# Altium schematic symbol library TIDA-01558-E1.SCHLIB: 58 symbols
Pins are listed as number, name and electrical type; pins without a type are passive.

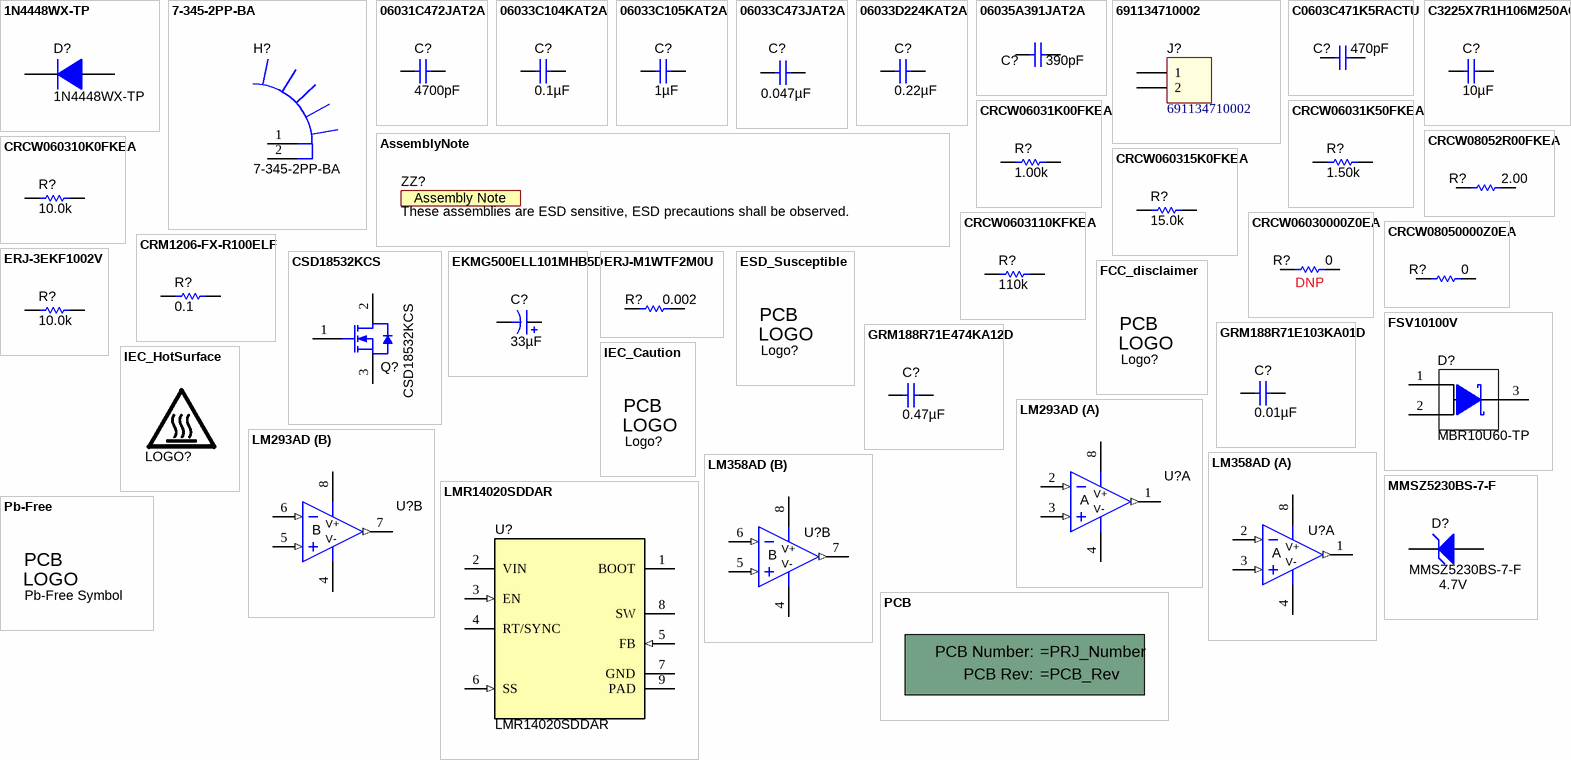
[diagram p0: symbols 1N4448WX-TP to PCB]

## 1N4448WX-TP
designator D?
Diode, Switching, 75 V, 0.25 A, SOD-323; Manufacturer: Micro Commercial Components; U/M: EA; Value: 75V; Value1: 0.25A; Io_A: 0.25; Vr_V: 75; TJmax_C: 150; SizeAreaWB_mm2: 8.695; SizeArea_mm2: 3.645; SizeX_mm: 2.7; SizeY_mm: 1.35; SizeZ_mm: 1; AEC Category: Q101; Green_Lifecycle: Not Set; Green_REACh: Incomplete
signal-integrity model Diode
footprint SOD-323
pins: 1 K, 2 A

## 7-345-2PP-BA
designator H?
Heatsink, TO-220, Black Anodized; Manufacturer: CTS Electrocomponents; SymbolCreator: a0799628
footprint HEATSINK_7-340-2PP (HEATSINK, DUAL TO-220)
pins: 1, 2

## 06031C472JAT2A
designator C?  ValueDisplayed: 4700pF  (hidden comment: 06031C472JAT2A)
CAP, CERM, 4700 pF, 100 V,+/- 5%, X7R, 0603; Manufacturer: AVX; Polarized: N; CompType: Capacitor; Value: 4700pF; U/M: EA; Cap_F: 0.0000000047; Tolerance_%: 5; ESR_ohm: 0.136; Value1: 0.136 ohm; VDC_V: 100; Value2: 100V; TaMin_C: -55; TaMax_C: 125; Cap_Case: 0603; SizeArea_mm2: 1.28; SizeAreaWB_mm2: 4.68; SizeX_mm: 1.6; SizeY_mm: 0.8; SizeZ_mm: 1; AEC Category: Q200; Green_Lifecycle: Active; Green_REACh: Passed
signal-integrity model Cap
simulation model Cap
footprint 0603
footprint 0603M
footprint 0603L
footprint 0603_HV
footprint 0603S
pins: 1, 2

## 06033C104KAT2A
designator C?  ValueDisplayed: 0.1µF  (hidden comment: 06033C104KAT2A)
CAP, CERM, 0.1 µF, 25 V,+/- 10%, X7R, 0603; Manufacturer: AVX; Polarized: N; CompType: Capacitor; Value: 0.1uF; U/M: EA; Cap_F: 0.0000001; Tolerance_%: 10; ESR_ohm: 0.05; Value1: 0.05 ohm; VDC_V: 25; Value2: 25V; TaMin_C: -55; TaMax_C: 125; Cap_Case: 0603; SizeArea_mm2: 1.28; SizeAreaWB_mm2: 4.68; SizeX_mm: 1.6; SizeY_mm: 0.8; SizeZ_mm: 1; AEC Category: Q200; Green_Lifecycle: Active; Green_REACh: Passed
signal-integrity model Cap
simulation model Cap
footprint 0603
footprint 0603M
footprint 0603L
footprint 0603_HV
footprint 0603S
pins: 1, 2

## 06033C105KAT2A
designator C?  ValueDisplayed: 1µF  (hidden comment: 06033C105KAT2A)
CAP, CERM, 1 µF, 25 V,+/- 10%, X7R, 0603; Manufacturer: AVX; Polarized: N; CompType: Capacitor; Value: 1uF; U/M: EA; Cap_F: 0.000001; Tolerance_%: 10; Value1: Unknown; VDC_V: 25; Value2: 25V; TaMin_C: -55; TaMax_C: 125; Cap_Case: 0603; SizeArea_mm2: 1.28; SizeAreaWB_mm2: 4.68; SizeX_mm: 1.6; SizeY_mm: 0.8; SizeZ_mm: 1; AEC Category: Q200
signal-integrity model Cap
simulation model Cap
footprint 0603
footprint 0603M
footprint 0603L
footprint 0603_HV
footprint 0603S
pins: 1, 2

## 06033C473JAT2A
designator C?  ValueDisplayed: 0.047µF  (hidden comment: 06033C473JAT2A)
CAP, CERM, 0.047 µF, 25 V,+/- 5%, X7R, 0603; Manufacturer: AVX; Polarized: N; CompType: Capacitor; Value: 0.047uF; U/M: EA; Cap_F: 0.000000047; Tolerance_%: 5; ESR_ohm: 0.052; Value1: 0.052 ohm; VDC_V: 25; Value2: 25V; TaMin_C: -55; TaMax_C: 125; Cap_Case: 0603; SizeArea_mm2: 1.28; SizeAreaWB_mm2: 4.68; SizeX_mm: 1.6; SizeY_mm: 0.8; SizeZ_mm: 1; AEC Category: Q200; Green_Lifecycle: Active; Green_REACh: Passed
signal-integrity model Cap
simulation model Cap
footprint 0603
footprint 0603M
footprint 0603L
footprint 0603_HV
footprint 0603S
pins: 1, 2

## 06033D224KAT2A
designator C?  ValueDisplayed: 0.22µF  (hidden comment: 06033D224KAT2A)
CAP, CERM, 0.22 µF, 25 V,+/- 10%, X5R, 0603; Manufacturer: AVX; Polarized: N; CompType: Capacitor; Value: 0.22uF; U/M: EA; Cap_F: 0.00000022; Tolerance_%: 10; ESR_ohm: 0.036; Value1: 0.036 ohm; VDC_V: 25; Value2: 25V; TaMin_C: -55; TaMax_C: 85; Cap_Case: 0603; SizeArea_mm2: 1.28; SizeAreaWB_mm2: 4.68; SizeX_mm: 1.6; SizeY_mm: 0.8; SizeZ_mm: 1; AEC Category: Q200; Green_Lifecycle: Active; Green_REACh: Passed
signal-integrity model Cap
simulation model Cap
footprint 0603
footprint 0603M
footprint 0603L
footprint 0603_HV
footprint 0603S
pins: 1, 2

## 06035A391JAT2A
designator C?  ValueDisplayed: 390pF  (hidden comment: 06035A391JAT2A)
CAP, CERM, 390 pF, 50 V,+/- 5%, C0G/NP0, 0603; Manufacturer: AVX; Polarized: N; CompType: Capacitor; Value: 390pF; U/M: EA; Cap_F: 0.00000000039; Tolerance_%: 5; ESR_ohm: 0.067; Value1: 0.067 ohm; VDC_V: 50; Value2: 50V; TaMin_C: -55; TaMax_C: 125; Cap_Case: 0603; SizeArea_mm2: 1.28; SizeAreaWB_mm2: 4.68; SizeX_mm: 1.6; SizeY_mm: 0.8; SizeZ_mm: 1; AEC Category: Q200; Green_Lifecycle: Not Set; Green_REACh: Incomplete
signal-integrity model Cap
simulation model Cap
footprint 0603
footprint 0603M
footprint 0603L
footprint 0603_HV
footprint 0603S
pins: 1, 2

## 691134710002
designator J?
WR-TBL Serie 1347 - 5.00 mm Horizontal Cable Entry with Pressure Clamp, 02p; Manufacturer: Wurth Elektronik; Pitch: 5 mm
footprint 691134710002 (Serie 1347 - 5.00 mm_2 pins)
pins: 1, 2

## AssemblyNote
designator ZZ?, comment These assemblies are ESD sensitive, ESD precautions shall be observed.  (no BOM)
SymbolCreator: codlsc; CompType: AssemblyNote
footprint AssemblyNote

## C0603C471K5RACTU
designator C?, comment ValueDisplayed: 470pF  (hidden comment: C0603C471K3RACTU)
CAP, CERM, 470 pF, 25 V,+/- 10%, X7R, 0603; Manufacturer: Kemet; Polarized: N; CompType: Capacitor; Value: 470pF; U/M: EA; Cap_F: 0.00000000047; Tolerance_%: 10; VDC_V: 25; Value2: 25V; TaMin_C: -55; TaMax_C: 125; Cap_Case: 0603; SizeArea_mm2: 1.28; SizeAreaWB_mm2: 4.68; SizeX_mm: 1.6; SizeY_mm: 0.8; SizeZ_mm: 1; AEC Category: Q200; Green_Lifecycle: Active; Green_REACh: Passed
signal-integrity model Cap
simulation model Cap
footprint 0603
footprint 0603M
footprint 0603L
footprint 0603_HV
footprint 0603S
pins: 1, 2

## C3225X7R1H106M250AC
designator C?  ValueDisplayed: 10µF  (hidden comment: C3225X7R1H106M250AC)
CAP, CERM, 10 µF, 50 V,+/- 20%, X7R, 1210; Manufacturer: TDK; Polarized: N; CompType: Capacitor; Value: 10uF; U/M: EA; Cap_F: 0.00001; Tolerance_%: 20; VDC_V: 50; Value2: 50V; TaMin_C: -55; TaMax_C: 125; Cap_Case: 1210; SizeArea_mm2: 8; SizeAreaWB_mm2: 14.7; SizeX_mm: 3.2; SizeY_mm: 2.5; SizeZ_mm: 2.8; AEC Category: Q200; Green_Lifecycle: Active; Green_REACh: Passed
signal-integrity model Cap
simulation model Cap
footprint 1210_280
pins: 1, 2

## CRCW06031K00FKEA
designator R?  ValueDisplayed: 1.00k  (hidden comment: CRCW06031K00FKEA)
RES, 1.00 k, 1%, 0.1 W, 0603; Manufacturer: Vishay-Dale; CompType: Resistor; Value: 1.00k; Res_ohm: 1000; Value_Code: 1k00; Tolerance_%: 1; Power_W: 0.1; Value2: 0.1W; VDC_V: 75; TempCo: 100 ppm/C; SizeArea_mm2: 1.28; SizeX_mm: 1.6; SizeY_mm: 0.8; EIA_Code: E96; U/M: EA; AEC Category: Q200; Green_Lifecycle: Active; Green_REACh: Passed
signal-integrity model Resistor
simulation model Resistor
footprint 0603
footprint 0603M
footprint 0603L
footprint 0603_HV
footprint 0603S
pins: 1, 2

## CRCW06031K50FKEA
designator R?  ValueDisplayed: 1.50k  (hidden comment: CRCW06031K50FKEA)
RES, 1.50 k, 1%, 0.1 W, 0603; Manufacturer: Vishay-Dale; CompType: Resistor; Value: 1.50k; Res_ohm: 1500; Value_Code: 1k50; Tolerance_%: 1; Power_W: 0.1; Value2: 0.1W; VDC_V: 75; TempCo: 100 ppm/C; SizeArea_mm2: 1.28; SizeX_mm: 1.6; SizeY_mm: 0.8; EIA_Code: E96; U/M: EA; AEC Category: Q200; Green_Lifecycle: Active; Green_REACh: Passed
signal-integrity model Resistor
simulation model Resistor
footprint 0603
footprint 0603M
footprint 0603L
footprint 0603_HV
footprint 0603S
pins: 1, 2

## CRCW08052R00FKEA
designator R?  ValueDisplayed: 2.00  (hidden comment: CRCW08052R00FKEA)
RES, 2.00, 1%, 0.125 W, 0805; Manufacturer: Vishay-Dale; CompType: Resistor; Value: 2.00; Res_ohm: 2; Value_Code: 2R00; Tolerance_%: 1; Power_W: 0.125; Value2: 0.125W; VDC_V: 150; TempCo: 100 ppm/C; SizeArea_mm2: 2.5; SizeY_mm: 1.25; SizeZ_mm: 1.45; EIA_Code: E96; U/M: EA; AEC Category: Q200
signal-integrity model Resistor
simulation model Resistor
footprint 0805_HV
footprint 0805_HV1
footprint 0805
footprint 0805M
footprint 0805L
pins: 1, 2

## CRCW060310K0FKEA
designator R?  ValueDisplayed: 10.0k  (hidden comment: CRCW060310K0FKEA)
RES, 10.0 k, 1%, 0.1 W, 0603; Manufacturer: Vishay-Dale; CompType: Resistor; Value: 10.0k; Res_ohm: 10000; Value_Code: 10k0; Tolerance_%: 1; Power_W: 0.1; Value2: 0.1W; VDC_V: 75; TempCo: 100 ppm/C; SizeArea_mm2: 1.28; SizeX_mm: 1.6; SizeY_mm: 0.8; EIA_Code: E96; U/M: EA; AEC Category: Q200; Green_Lifecycle: Active; Green_REACh: Passed
signal-integrity model Resistor
simulation model Resistor
footprint 0603
footprint 0603M
footprint 0603L
footprint 0603_HV
footprint 0603S
pins: 1, 2

## CRCW060315K0FKEA
designator R?  ValueDisplayed: 15.0k  (hidden comment: CRCW060315K0FKEA)
RES, 15.0 k, 1%, 0.1 W, 0603; Manufacturer: Vishay-Dale; CompType: Resistor; Value: 15.0k; Res_ohm: 15000; Value_Code: 15k0; Tolerance_%: 1; Power_W: 0.1; Value2: 0.1W; VDC_V: 75; TempCo: 100 ppm/C; SizeArea_mm2: 1.28; SizeX_mm: 1.6; SizeY_mm: 0.8; EIA_Code: E96; U/M: EA; AEC Category: Q200; Green_Lifecycle: Active; Green_REACh: Passed
signal-integrity model Resistor
simulation model Resistor
footprint 0603
footprint 0603M
footprint 0603L
footprint 0603_HV
footprint 0603S
pins: 1, 2

## CRCW0603110KFKEA
designator R?  ValueDisplayed: 110k  (hidden comment: CRCW0603110KFKEA)
RES, 110 k, 1%, 0.1 W, 0603; Manufacturer: Vishay-Dale; CompType: Resistor; Value: 110k; Res_ohm: 110000; Tolerance_%: 1; Power_W: 0.1; Value2: 0.1W; VDC_V: 75; TempCo: 100 ppm/C; SizeArea_mm2: 1.28; SizeX_mm: 1.6; SizeY_mm: 0.8; EIA_Code: E96; U/M: EA; AEC Category: Q200; Green_Lifecycle: Active; Green_REACh: Passed
signal-integrity model Resistor
simulation model Resistor
footprint 0603
footprint 0603M
footprint 0603L
footprint 0603_HV
footprint 0603S
pins: 1, 2

## CRCW06030000Z0EA
designator R?  ValueDisplayed: 0  Installation: DNP  (hidden comment: CRCW06030000Z0EA)
RES, 0, 5%, 0.1 W, 0603; Manufacturer: Vishay-Dale; CompType: Resistor; Value: 0; Value_Code: 0000; Tolerance_%: 5; Power_W: 0.1; Value2: 0.1W; VDC_V: 75; TempCo: 200 ppm/C; SizeArea_mm2: 1.28; SizeX_mm: 1.6; SizeY_mm: 0.8; SizeZ_mm: 1; EIA_Code: E24; U/M: EA; AEC Category: Q200; Green_Lifecycle: Active; Green_REACh: Passed
signal-integrity model Resistor
simulation model Resistor
footprint 0603
footprint 0603M
footprint 0603L
footprint 0603_HV
footprint 0603S
pins: 1, 2

## CRCW08050000Z0EA
designator R?  ValueDisplayed: 0  (hidden comment: CRCW08050000Z0EA)
RES, 0, 5%, 0.125 W, 0805; Manufacturer: Vishay-Dale; CompType: Resistor; Value: 0; Value_Code: 0000; Tolerance_%: 5; Power_W: 0.125; Value2: 0.125W; VDC_V: 150; TempCo: 200 ppm/C; SizeArea_mm2: 2.5; SizeX_mm: 2; SizeY_mm: 1.25; SizeZ_mm: 1.45; EIA_Code: E24; U/M: EA; AEC Category: Q200; Green_Lifecycle: Active; Green_REACh: Passed
signal-integrity model Resistor
simulation model Resistor
footprint 0805_HV
footprint 0805_HV1
footprint 0805
footprint 0805M
footprint 0805L
pins: 1, 2

## CRM1206-FX-R100ELF
designator R?  ValueDisplayed: 0.1  (hidden comment: CRM1206-FX-R100ELF)
RES, 0.1, 1%, 0.5 W, 1206; Manufacturer: Bourns; CompType: Resistor; Value: 0.1; Value_Code: R100; Tolerance_%: 1; Power_W: 0.5; Value2: 0.5W; VDC_V: 0; TempCo: 150 ppm/C; SizeArea_mm2: 5.12; SizeX_mm: 3.2; SizeY_mm: 1.6; SizeZ_mm: 1.35; EIA_Code: E96; U/M: EA; AEC Category: Q200
signal-integrity model Resistor
simulation model Resistor
footprint 1206
footprint 1206M
footprint 1206L
pins: 1, 2

## CSD18532KCS
designator Q?
MOSFET, N-CH, 60 V, 100 A, KCS0003B (TO-220-3); Manufacturer: Texas Instruments; Alternate Manufacturer: None; U/M: EA; ChType: N; Value: 60V; VdsMax_V: 60; Value1: 0.0053 ohm; Rdson45_ohm: 0.0053; Value2: 44 nC; QgTyp_nC: 44; Vgs_V: 20; IdsMax_A: 100; SizeAreaWB_mm2: 79.648; SizeArea_mm2: 46.228; SizeX_mm: 4.55; SizeY_mm: 10.16; SizeZ_mm: 20.45; AEC Category: Q101
footprint TO-220AB_Horizontal_100mil (High Voltage staggered pins)
footprint KCS0003B_FormA
pins: 1 G, 2 D, 3 S
1 alternate drawing of the same symbol

## EKMG500ELL101MHB5D
designator C?, comment ValueDisplayed: 33µF  (hidden comment: 63SXE33M)
CAP, AL, 33 µF, 63 V, +/- 20%, TH; Manufacturer: Panasonic Electronic Components; Polarized: Y; CompType: Capacitor; Value: 33uF; U/M: EA; Cap_F: 0.0001; Tolerance_%: 20; VDC_V: 63; Value2: 63V; IRMS_A: 0.18; TaMin_C: -55; TaMax_C: 105; Cap_Case: 8x11.5mm; SizeAreaWB_mm2: 100; SizeArea_mm2: 64; SizeX_mm: 8; SizeZ_mm: 13; AEC Category: Q200; AEC Qualified: N
signal-integrity model Cap
simulation model Cap
footprint Chemi-Con_800x1150
pins: 1 +, 2 -

## ERJ-3EKF1002V
designator R?  ValueDisplayed: 10.0k  (hidden comment: ERJ-3EKF1002V)
RES, 10.0 k, 1%, 0.1 W, 0603; Manufacturer: Panasonic; CompType: Resistor; Value: 10.0k; Res_ohm: 10000; Value_Code: 10k0; Tolerance_%: 1; Power_W: 0.1; Value2: 0.1W; VDC_V: 75; TempCo: 100 ppm/C; SizeArea_mm2: 1.28; SizeX_mm: 1.6; SizeY_mm: 0.8; EIA_Code: E96; U/M: EA; AEC Category: Q200; Green_Lifecycle: Active; Green_REACh: Passed
signal-integrity model Resistor
simulation model Resistor
footprint 0603
footprint 0603M
footprint 0603L
footprint 0603_HV
footprint 0603S
pins: 1, 2

## ERJ-M1WTF2M0U
designator R?, comment ValueDisplayed: 0.002  (hidden comment: CRE2512-FZ-R002E-3)
RES SMD 2 MOHM 1% 3W 2512; Manufacturer: Bourns Inc.; CompType: Resistor; Value: 0.002; Value_Code: 2L000; Tolerance_%: 1; TempCo: ppm/C; SizeArea_mm2: 20.16; SizeX_mm: 6.3; SizeY_mm: 3.2; SizeZ_mm: 0.71; U/M: EA; AEC Category: Q200
signal-integrity model Resistor
simulation model Resistor
footprint 2512
footprint 2512M
footprint 2512L
pins: 1, 2

## ESD_Susceptible
designator Logo?, comment ESD Susceptible  (value not drawn)  (no BOM)
ESD Susceptible Symbol; SymbolCreator: a0412235
footprint ESD_Overlay_Large
footprint ESD_Overlay_Medium
footprint ESD_Overlay_Small

## FCC_disclaimer
designator Logo?, comment FCC disclaimer  (value not drawn)  (no BOM)
FCC_disclaimer; SymbolCreator: a0412235
footprint FCC_disclaimer
footprint FCC_disclaimer_stacked

## FSV10100V
designator D?, comment MBR10U60-TP
DIODE SCHOTTKY 60V 10A TO277; Manufacturer: Micro Commercial Co; U/M: EA; Vf_V: 500mV; Io_A: 10; TJmax_C: 150; SizeAreaWB_mm2: 57.375; SizeArea_mm2: 30.875; SizeX_mm: 6.5; SizeY_mm: 4.75; SizeZ_mm: 1.2; AEC Category: Q101; AEC Qualified: Y; Green_Lifecycle: Not Set; Green_REACh: Incomplete
signal-integrity model Diode
footprint TO-277A
pins: 1 A, 2 A, 3 K

## GRM188R71E103KA01D
designator C?  ValueDisplayed: 0.01µF  (hidden comment: GRM188R71E103KA01D)
CAP, CERM, 0.01 µF, 25 V,+/- 10%, X7R, 0603; Manufacturer: MuRata; Polarized: N; CompType: Capacitor; Value: 0.01uF; U/M: EA; Cap_F: 0.00000001; Tolerance_%: 10; Value1: Unknown; VDC_V: 25; Value2: 25V; TaMin_C: -55; TaMax_C: 125; Cap_Case: 0603; SizeArea_mm2: 1.28; SizeAreaWB_mm2: 4.68; SizeX_mm: 1.6; SizeY_mm: 0.8; SizeZ_mm: 1; AEC Category: Q200; Green_Lifecycle: Active; Green_REACh: Passed
signal-integrity model Cap
simulation model Cap
footprint 0603
footprint 0603M
footprint 0603L
footprint 0603_HV
footprint 0603S
pins: 1, 2

## GRM188R71E474KA12D
designator C?  ValueDisplayed: 0.47µF  (hidden comment: GRM188R71E474KA12D)
CAP, CERM, 0.47 µF, 25 V,+/- 10%, X7R, 0603; Manufacturer: MuRata; Polarized: N; CompType: Capacitor; Value: 0.47uF; U/M: EA; Cap_F: 0.00000047; Tolerance_%: 10; VDC_V: 25; Value2: 25V; TaMin_C: -55; TaMax_C: 125; Cap_Case: 0603; SizeArea_mm2: 1.28; SizeAreaWB_mm2: 4.68; SizeX_mm: 1.6; SizeY_mm: 0.8; SizeZ_mm: 1; AEC Category: Q200; Green_Lifecycle: Active; Green_REACh: Passed
signal-integrity model Cap
simulation model Cap
footprint 0603
footprint 0603M
footprint 0603L
footprint 0603_HV
footprint 0603S
pins: 1, 2

## IEC_Caution
designator Logo?, comment CAUTION.  READ USER GUIDE BEFORE USE  (value not drawn)  (no BOM)
IEC 61010-1 Caution Warning; SymbolCreator: a0412235
footprint IEC_Caution_Large
footprint IEC_Caution_Medium
footprint IEC_Caution_Small

## IEC_HotSurface
designator LOGO?, comment CAUTION HOT SURFACE  (value not drawn)  (no BOM)
IEC 61010-1 Hot Surface Warning; SymbolCreator: a0412235
footprint IEC_HotSurface_Large
footprint IEC_HotSurface_Medium
footprint IEC_HotSurface_Small

## LM293AD
designator U?  (value not drawn)
Dual Comparator, D0008A; Manufacturer: Texas Instruments; CompType: OpAmp IC
footprint D0008A_N
footprint D0008A_M
footprint D0008A_L
simulation model LM293A (SUBCKT)
pins on every part: 4 V- (power), 8 V+ (power)
part A pins: 1 OUT (out), 2 IN- (in), 3 IN+ (in)
part B pins: 5 IN+ (in), 6 IN- (in), 7 OUT (out)
1 alternate drawing of the same symbol

## LM358AD
designator U?  (value not drawn)
Dual Low Power Op Amp, D0008A; Manufacturer: Texas Instruments; CompType: OpAmp IC
footprint D0008A_N
footprint D0008A_M
footprint D0008A_L
simulation model LM358 (SUBCKT)
pins on every part: 4 V- (power), 8 V+ (power)
part A pins: 1 OUT (out), 2 IN- (in), 3 IN+ (in)
part B pins: 5 IN+ (in), 6 IN- (in), 7 OUT (out)
1 alternate drawing of the same symbol

## LMR14020SDDAR
designator U?
SIMPLE SWITCHER, 4V to 40V, 2A 2.2MHz Step-Down Regulator with Low IQ, DDA0008E (SOIC-8); Manufacturer: Texas Instruments; SymbolCreator: Altium; SizeArea_mm2: 31; SizeAreaWB_mm2: 57.4; SizeX_mm: 5; SizeY_mm: 6.2; SizeZ_mm: 1.7; CompType: IC; U/M: EA
footprint DDA0008E_N
footprint DDA0008E_M
footprint DDA0008E_L
pins: 1 BOOT, 2 VIN (power), 3 EN (in), 4 RT/SYNC, 5 FB (in), 6 SS (in), 7 GND (power), 8 SW (power), 9 PAD (power)

## MMSZ5230BS-7-F
designator D?  value 4.7V
Diode, Zener, 4.7 V, 200 mW, SOD-323; Manufacturer: Diodes Inc.; SymbolCreator: a0412235; U/M: EA; Power_W: 0.2; Vz_V: 4.7; Value1: 0.2W; RJA_CperW: 350; SizeAreaWB_mm2: 8.695; SizeArea_mm2: 3.645; SizeX_mm: 2.7; SizeY_mm: 1.35; SizeZ_mm: 1; AEC Category: Q101; Green_Lifecycle: Active; Green_REACh: Passed
signal-integrity model Diode
footprint SOD-323
pins: 1 K, 2 A

## Pb-Free
designator Logo?, comment Pb-Free Symbol  (no BOM)
SymbolCreator: a0412235
footprint Pb-Free_Overlay_Medium
footprint Pb-Free_Overlay_Small

## PCB
designator !PCB?, comment Printed Circuit Board  (value not drawn)  (mechanical)
Manufacturer: Any; SymbolCreator: a0412235; CompType: PCB
1 alternate drawing of the same symbol

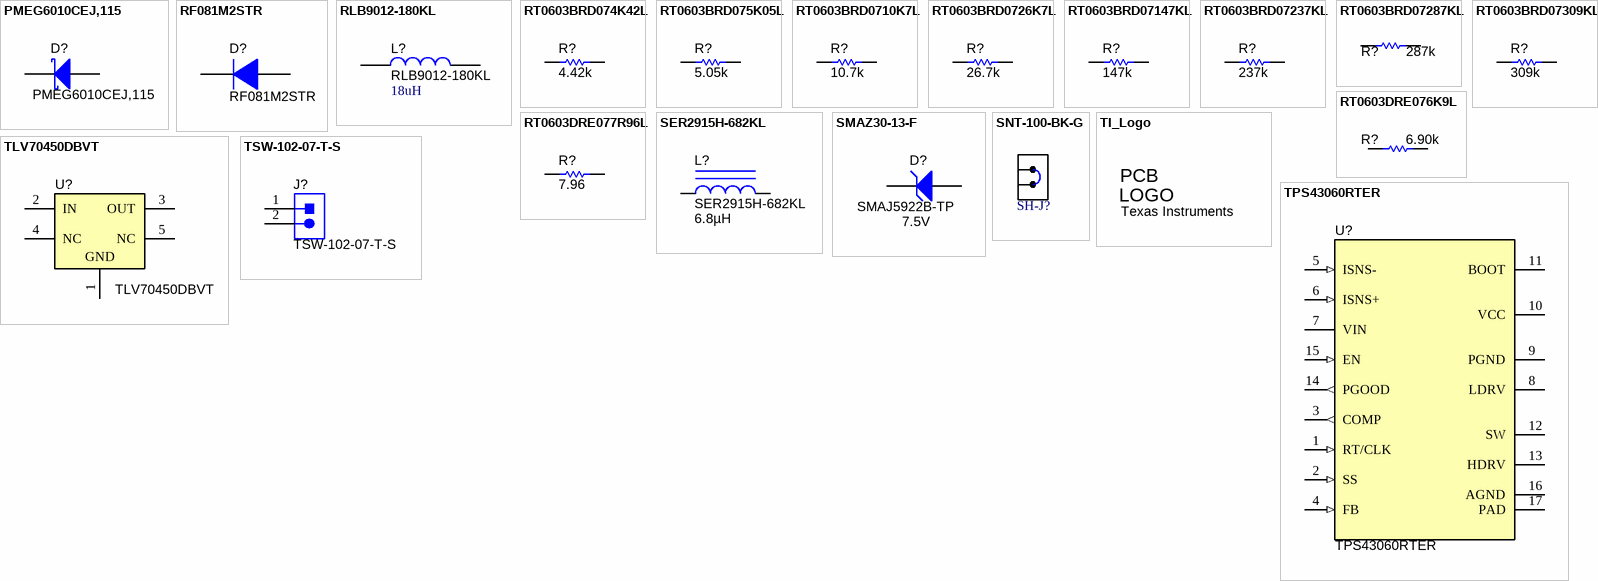
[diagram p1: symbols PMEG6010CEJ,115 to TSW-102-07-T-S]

## PMEG6010CEJ,115
designator D?
Diode, Schottky, 60 V, 1 A, SOD-323F; Manufacturer: Nexperia; U/M: EA; Vf_V: 0.66; Value: 60V; Value1: 1A; Value2: 0.66V; Io_A: 1; Vr_V: 60; TJmax_C: 150; SizeAreaWB_mm2: 7.875; SizeArea_mm2: 3.125; SizeX_mm: 2.5; SizeY_mm: 1.25; SizeZ_mm: 0.8; AEC Category: Q101; Green_Lifecycle: Not Set; Green_REACh: Incomplete
signal-integrity model Diode
footprint SOD-323F
pins: 1 K, 2 A

## RF081M2STR
designator D?
Diode, Fast Rectifier, 200 V, 0.8 A, SOD-123; Manufacturer: Rohm; U/M: EA; Vf_V: 0.95; Value: 200V; Value1: 0.8A; Value2: 0.95V; Io_A: 0.8; Vr_V: 200; TJmax_C: 150; SizeAreaWB_mm2: 13.095; SizeArea_mm2: 6.545; SizeX_mm: 3.85; SizeY_mm: 1.7; SizeZ_mm: 1.35; AEC Category: Q101; Green_Lifecycle: Not Set; Green_REACh: Incomplete
signal-integrity model Diode
footprint SOD-123
pins: 1 K, 2 A

## RLB9012-180KL
designator L?  value 18uH
INDUCTOR, FIXED, 18uH, 10%, 2.66A, 11MHz, TH, 2-PIN; Manufacturer: BOURNS; SymbolCreator: x0199378
footprint IND_RLB9012 (INDUCTOR, RLB9012 SERIES, 2-PIN)
pins: 1, 2

## RT0603BRD074K42L
designator R?  ValueDisplayed: 4.42k  (hidden comment: RT0603BRD074K42L)
RES, 4.42 k, 0.1%, 0.1 W, 0603; Manufacturer: Yageo America; CompType: Resistor; Value: 4.42k; Res_ohm: 4420; Value_Code: 4k42; Tolerance_%: 0.1; Value2: 0.1W; VDC_V: 75; TempCo: 25 ppm/C; SizeArea_mm2: 1.28; SizeX_mm: 1.6; SizeY_mm: 0.8; SizeZ_mm: 1; EIA_Code: E192; U/M: EA; AEC Category: Q200
signal-integrity model Resistor
simulation model Resistor
footprint 0603
footprint 0603M
footprint 0603L
footprint 0603_HV
footprint 0603S
pins: 1, 2

## RT0603BRD075K05L
designator R?  ValueDisplayed: 5.05k  (hidden comment: RT0603BRD075K05L)
RES, 5.05 k, 0.1%, 0.1 W, 0603; Manufacturer: Yageo America; CompType: Resistor; Value: 5.05k; Res_ohm: 5050; Value_Code: 5k05; Tolerance_%: 0.1; Value2: 0.1W; VDC_V: 75; TempCo: 25 ppm/C; SizeArea_mm2: 1.28; SizeX_mm: 1.6; SizeY_mm: 0.8; SizeZ_mm: 1; EIA_Code: E192; U/M: EA; AEC Category: Q200
signal-integrity model Resistor
simulation model Resistor
footprint 0603
footprint 0603M
footprint 0603L
footprint 0603_HV
footprint 0603S
pins: 1, 2

## RT0603BRD0710K7L
designator R?  ValueDisplayed: 10.7k  (hidden comment: RT0603BRD0710K7L)
RES, 10.7 k, 0.1%, 0.1 W, 0603; Manufacturer: Yageo America; CompType: Resistor; Value: 10.7k; Res_ohm: 10700; Value_Code: 10k7; Tolerance_%: 0.1; Value2: 0.1W; VDC_V: 75; TempCo: 25 ppm/C; SizeArea_mm2: 1.28; SizeX_mm: 1.6; SizeY_mm: 0.8; SizeZ_mm: 1; EIA_Code: E192; U/M: EA; AEC Category: Q200
signal-integrity model Resistor
simulation model Resistor
footprint 0603
footprint 0603M
footprint 0603L
footprint 0603_HV
footprint 0603S
pins: 1, 2

## RT0603BRD0726K7L
designator R?  ValueDisplayed: 26.7k  (hidden comment: RT0603BRD0726K7L)
RES, 26.7 k, 0.1%, 0.1 W, 0603; Manufacturer: Yageo America; CompType: Resistor; Value: 26.7k; Res_ohm: 26700; Value_Code: 26k7; Tolerance_%: 0.1; Value2: 0.1W; VDC_V: 75; TempCo: 25 ppm/C; SizeArea_mm2: 1.28; SizeX_mm: 1.6; SizeY_mm: 0.8; SizeZ_mm: 1; EIA_Code: E192; U/M: EA; AEC Category: Q200
signal-integrity model Resistor
simulation model Resistor
footprint 0603
footprint 0603M
footprint 0603L
footprint 0603_HV
footprint 0603S
pins: 1, 2

## RT0603BRD07147KL
designator R?  ValueDisplayed: 147k  (hidden comment: RT0603BRD07147KL)
RES, 147 k, 0.1%, 0.1 W, 0603; Manufacturer: Yageo America; CompType: Resistor; Value: 147k; Res_ohm: 147000; Tolerance_%: 0.1; Value2: 0.1W; VDC_V: 75; TempCo: 25 ppm/C; SizeArea_mm2: 1.28; SizeX_mm: 1.6; SizeY_mm: 0.8; SizeZ_mm: 1; EIA_Code: E192; U/M: EA; AEC Category: Q200
signal-integrity model Resistor
simulation model Resistor
footprint 0603
footprint 0603M
footprint 0603L
footprint 0603_HV
footprint 0603S
pins: 1, 2

## RT0603BRD07237KL
designator R?  ValueDisplayed: 237k  (hidden comment: RT0603BRD07237KL)
RES, 237 k, 0.1%, 0.1 W, 0603; Manufacturer: Yageo America; CompType: Resistor; Value: 237k; Res_ohm: 237000; Tolerance_%: 0.1; Value2: 0.1W; VDC_V: 75; TempCo: 25 ppm/C; SizeArea_mm2: 1.28; SizeX_mm: 1.6; SizeY_mm: 0.8; SizeZ_mm: 1; EIA_Code: E192; U/M: EA; AEC Category: Q200
signal-integrity model Resistor
simulation model Resistor
footprint 0603
footprint 0603M
footprint 0603L
footprint 0603_HV
footprint 0603S
pins: 1, 2

## RT0603BRD07287KL
designator R?  ValueDisplayed: 287k  (hidden comment: RT0603BRD07287KL)
RES, 287 k, 0.1%, 0.1 W, 0603; Manufacturer: Yageo America; CompType: Resistor; Value: 287k; Res_ohm: 287000; Tolerance_%: 0.1; Value2: 0.1W; VDC_V: 75; TempCo: 25 ppm/C; SizeArea_mm2: 1.28; SizeX_mm: 1.6; SizeY_mm: 0.8; SizeZ_mm: 1; EIA_Code: E192; U/M: EA; AEC Category: Q200
signal-integrity model Resistor
simulation model Resistor
footprint 0603
footprint 0603M
footprint 0603L
footprint 0603_HV
footprint 0603S
pins: 1, 2

## RT0603BRD07309KL
designator R?  ValueDisplayed: 309k  (hidden comment: RT0603BRD07309KL)
RES, 309 k, 0.1%, 0.1 W, 0603; Manufacturer: Yageo America; CompType: Resistor; Value: 309k; Res_ohm: 309000; Tolerance_%: 0.1; Value2: 0.1W; VDC_V: 75; TempCo: 25 ppm/C; SizeArea_mm2: 1.28; SizeX_mm: 1.6; SizeY_mm: 0.8; SizeZ_mm: 1; EIA_Code: E192; U/M: EA; AEC Category: Q200
signal-integrity model Resistor
simulation model Resistor
footprint 0603
footprint 0603M
footprint 0603L
footprint 0603_HV
footprint 0603S
pins: 1, 2

## RT0603DRE076K9L
designator R?  ValueDisplayed: 6.90k  (hidden comment: RT0603DRE076K9L)
RES, 6.90 k, 0.5%, 0.1 W, 0603; Manufacturer: Yageo America; CompType: Resistor; Value: 6.90k; Res_ohm: 6900; Value_Code: 6k90; Tolerance_%: 0.5; Power_W: 0.1; Value2: 0.1W; VDC_V: 75; TempCo: 50 ppm/C; SizeArea_mm2: 1.28; SizeX_mm: 1.6; SizeY_mm: 0.8; SizeZ_mm: 1; EIA_Code: E192; U/M: EA; AEC Category: Q200
signal-integrity model Resistor
simulation model Resistor
footprint 0603
footprint 0603M
footprint 0603L
footprint 0603_HV
footprint 0603S
pins: 1, 2

## RT0603DRE077R96L
designator R?  ValueDisplayed: 7.96  (hidden comment: RT0603DRE077R96L)
RES, 7.96, 0.5%, 0.1 W, 0603; Manufacturer: Yageo America; CompType: Resistor; Value: 7.96; Value_Code: 7R96; Tolerance_%: 0.5; Power_W: 0.1; Value2: 0.1W; VDC_V: 75; TempCo: 50 ppm/C; SizeArea_mm2: 1.28; SizeX_mm: 1.6; SizeY_mm: 0.8; SizeZ_mm: 1; EIA_Code: E192; U/M: EA; AEC Category: Q200
signal-integrity model Resistor
simulation model Resistor
footprint 0603
footprint 0603M
footprint 0603L
footprint 0603_HV
footprint 0603S
pins: 1, 2

## SER2915H-682KL
designator L?  ValueDisplayed: 6.8µH
Inductor, Shielded E Core, Ferrite, 6.8uH, 30A, 0.00186 ohm, SMD; Manufacturer: Coilcraft; Ind_H: 6.8E-6; Imax_A: 30; Irms: 30A @ 40C rise; Isat: 36.2A @ 30% inductance drop; U/M: EA
signal-integrity model Inductor
simulation model Inductor
footprint SER2915
pins: 1, 2

## SMAZ30-13-F
designator D?, comment SMAJ5922B-TP  value 7.5V
DIODE ZENER 7.5V 1.5W DO214AC; Manufacturer: Micro Commercial Co; SymbolCreator: a0412235; U/M: EA; Power_W: 1; RJA_CperW: 100; SizeAreaWB_mm2: 37.3428; SizeArea_mm2: 16.3228; SizeX_mm: 5.59; SizeY_mm: 2.92; SizeZ_mm: 2.87; AEC Category: Q101; AEC Qualified: N
signal-integrity model Diode
footprint SMA
pins: 1 K, 2 A

## SNT-100-BK-G
designator SH-J?  (value not drawn)
Shunt, 100mil, Gold plated, Black; Manufacturer: Samtec; Alternate Manufacturer: 3M; Alternate PartNumber: 969102-0000-DA; Value: 1x2; Note: You can "mate" this to a header by matching the designator.  i.e. use SH-J3 for header J3; Green_Lifecycle: Active; Green_REACh: Passed
footprint SNT-100-BK-G

## TI_Logo
designator Logo?, comment Texas Instruments  (no BOM)
Texas Instrument Corporate Signature; SymbolCreator: codlsc
footprint TI_Stacked_SolderMask_Medium
footprint TI_Stacked_SolderMask_Small
footprint TI_Stacked_Overlay_Medium
footprint TI_Stacked_Overlay_Small
footprint TI_Horizontal_SolderMask_Medium
footprint TI_Horizontal_SolderMask_Small
footprint TI_Horizontal_Overlay_Medium
footprint TI_Horizontal_Overlay_Small
footprint TI_Symbol_SolderMask_Small
footprint TI_Symbol_Overlay_Medium
footprint TI_Symbol_Overlay_Small
footprint TI_Symbol_SolderMask_Medium

## TLV70450DBVT
designator U?
Single Output LDO, 150 mA, Fixed 5 V Output, 2.5 to 24 V Input, with Ultra-Low IQ, 5-pin SOT-23 (DBV), -40 to 125 degC, Green (RoHS & no Sb/Br); Manufacturer: Texas Instruments; Alternate PartNumber: Equivalent; Accuracy(%): 2; Fixed Output Options(V): 5; Iout(Max)(A): 0.15; Iq(Typ)(mA): 0.003; SubFamily: Single Channel LDO; Vdo(Typ)(mV): 400; Vin(Max)(V): 24; Vin(Min)(V): 2.5
footprint DBV0005A_N (SOT23, 5-Leads, Body 2.9x1.6mm, Pitch 0.95mm, IPC Medium Density)
footprint DBV0005A_L (SOT23, 5-Leads, Body 2.9x1.6mm, Pitch 0.95mm, IPC High Density)
footprint DBV0005A_M (SOT23, 5-Leads, Body 2.9x1.6mm, Pitch 0.95mm, IPC Low Density)
pins: 1 GND (power) "Ground", 2 IN (power) "Unregulated input voltage", 3 OUT (power) "Regulated output voltage. Any capacitor 1 uF or greater between this pin and ground is needed for stability", 4 NC "No connection. This pin can be left open or tied to ground for improved thermal performance", 5 NC "No connection. This pin can be left open or tied to ground for improved thermal performance"

## TPS43060RTER
designator U?
Low Iq, Synchronous Boost Controller with Wide Input Voltage and 7.5V Gate Drive for Standard FETs, RTE0016E (WQFN-16); Alternate PartNumber: TPS43060RTET; Manufacturer: Texas Instruments; SymbolCreator: a0411947; SizeArea_mm2: 9; SizeAreaWB_mm2: 16; SizeX_mm: 3; SizeZ_mm: 0.8; CompType: IC; U/M: EA; Green_Lifecycle: Active; Green_REACh: Passed
footprint RTE0016E
footprint RTE0016E_NV
pins: 1 RT/CLK (in), 2 SS (in), 3 COMP (out), 4 FB (in), 5 ISNS- (in), 6 ISNS+ (in), 7 VIN (power), 8 LDRV (power), 9 PGND (power), 10 VCC (power), 11 BOOT, 12 SW (power), 13 HDRV (power), 14 PGOOD (out), 15 EN (in), 16 AGND (power), 17 PAD (power)

## TSW-102-07-T-S
designator J?
Header, 2.54 mm, 2x1, Tin, TH; Manufacturer: Samtec; SymbolCreator: a0412235; Pitch_mm: 2.54; Gender: Male; Shrouded: N; Row_Count: 1; Current_A: 6.3; Voltage_V: 550; Cert_CSA: Y
footprint Samtec_TSW-102-07-T-S
pins: 1, 2
1 alternate drawing of the same symbol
